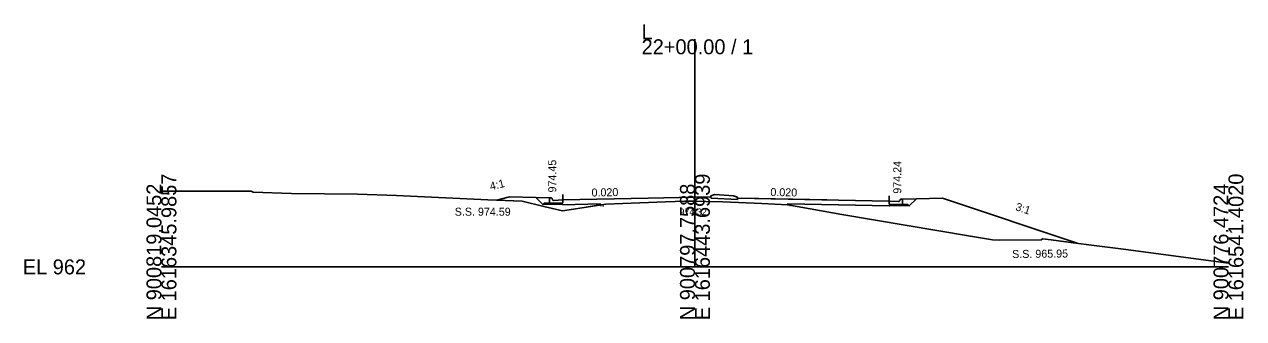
# Model space of a CAD drawing. Extents: x 1009 to 7438, y -1586 to 7964.
# Drawn here: x 2009.2 to 2237.7, y -86 to -30.8 of the extents above; entities that cross this region are included whole.
import ezdxf

# ---------------------------------------------------------------- set-up
doc = ezdxf.new("R2010")
doc.units = 0
for name, color, linetype in [('Exist Cross Section Cell', 7, 'Continuous'), ('Exist XS Center Line Elevation Label', 7, 'Continuous'), ('Exist XS Ground Line', 7, 'Continuous'), ('Prop XS Dump Level', 7, 'Continuous'), ('Prop XS Earthwork Shape', 7, 'Continuous'), ('Prop XS EOT Tick Mark', 7, 'Continuous'), ('Prop XS Finish Grade', 7, 'Continuous'), ('Prop XS Finish Grade CurbGutter', 7, 'Continuous'), ('Prop XS Finish Grade Earthwork', 7, 'Continuous'), ('Prop XS Finish Grade Pavement', 7, 'Continuous'), ('Prop XS Hydro Elevations', 7, 'Continuous'), ('Prop XS Pvmt Edge Slope', 7, 'Continuous'), ('Prop XS SE Text', 7, 'Continuous'), ('Prop XS Side Slope Text', 7, 'Continuous'), ('Prop XS SS Elevation Text', 7, 'Continuous'), ('Prop XS Subgrade CurbGutter', 7, 'Continuous'), ('Prop XS Subgrade Earthwork', 7, 'Continuous')]:
    doc.layers.add(name, color=color, linetype=linetype)

msp = doc.modelspace()

# ---------------------------------------------------------------- linework, layer by layer
at = {"layer": 'Exist Cross Section Cell'}
for p, q in [((2134.89, -76.27), (2134.89, -33.62)), ((2034.89, -76.27), (2134.89, -76.27)), ((2134.89, -76.27), (2234.89, -76.27))]:
    msp.add_line(p, q, dxfattribs=at)
at = {"layer": 'Exist XS Ground Line'}
for p, q in [((2034.89, -62.06), (2040.24, -62.05)), ((2040.24, -62.05), (2043.65, -62.06)), ((2043.65, -62.06), (2044.06, -62.08)), ((2044.06, -62.08), (2051.71, -62.09)), ((2051.71, -62.09), (2052.09, -62.24)), ((2052.09, -62.24), (2059.28, -62.49)), ((2059.28, -62.49), (2071.66, -62.67)), ((2071.66, -62.67), (2078.97, -62.92)), ((2078.97, -62.92), (2096.06, -63.69)), ((2096.06, -63.69), (2102.5, -63.94)), ((2102.5, -63.94), (2106.55, -64.95)), ((2129.35, -64.08), (2133.01, -63.98)), ((2133.01, -63.98), (2134.51, -63.94)), ((2134.51, -63.94), (2134.89, -63.95)), ((2134.89, -63.95), (2136.94, -64.01)), ((2106.55, -64.95), (2110.04, -65.76)), ((2110.04, -65.76), (2113.73, -65.21)), ((2113.73, -65.21), (2118.17, -64.51)), ((2118.17, -64.51), (2124.58, -64.26)), ((2124.58, -64.26), (2129.35, -64.08)), ((2136.94, -64.01), (2140.1, -64.07)), ((2140.1, -64.07), (2147.41, -64.42)), ((2147.41, -64.42), (2152.33, -64.66)), ((2152.33, -64.66), (2162.41, -66.43)), ((2162.41, -66.43), (2186.53, -70.54)), ((2186.53, -70.54), (2190.64, -71.2)), ((2190.64, -71.2), (2191.98, -71.27)), ((2191.98, -71.27), (2199.78, -71.23)), ((2199.78, -71.23), (2200.04, -71)), ((2200.04, -71), (2201.68, -71.21)), ((2201.68, -71.21), (2208.22, -72.06)), ((2208.22, -72.06), (2214.69, -72.9)), ((2214.69, -72.9), (2234.89, -75.57))]:
    msp.add_line(p, q, dxfattribs=at)
at = {"layer": 'Prop XS Dump Level'}
for p, q in [((2110.14, -63.7), (2126.14, -63.38)), ((2110.14, -63.7), (2126.14, -63.38)), ((2126.14, -63.38), (2134.89, -63.2)), ((2126.14, -63.38), (2134.89, -63.2)), ((2143.64, -63.38), (2159.64, -63.7)), ((2143.64, -63.38), (2159.64, -63.7))]:
    msp.add_line(p, q, dxfattribs=at)
at = {"layer": 'Prop XS Earthwork Shape'}
for points in [[(2110.04, -65.76), (2113.73, -65.21), (2117.14, -64.67), (2117.14, -64.47), (2110.14, -64.61), (2110.14, -64.53), (2106.39, -64.6), (2105.05, -63.26), (2100.14, -63.16), (2097.74, -63.76), (2102.5, -63.94), (2106.55, -64.95)], [(2181.31, -63.39), (2206.74, -71.87), (2201.68, -71.21), (2200.04, -71), (2199.78, -71.23), (2191.98, -71.27), (2190.64, -71.2), (2186.53, -70.54), (2162.41, -66.43), (2152.33, -64.66), (2152.28, -64.65), (2152.28, -64.46), (2171.31, -64.85), (2171.31, -64.76), (2175.06, -64.83), (2176.4, -63.49)]]:
    msp.add_lwpolyline(points, close=True, dxfattribs=at)
at = {"layer": 'Prop XS EOT Tick Mark'}
for p, q in [((2110.14, -63.7), (2110.14, -62.7)), ((2171.31, -63.93), (2171.31, -62.93))]:
    msp.add_line(p, q, dxfattribs=at)
at = {"layer": 'Prop XS Finish Grade'}
for p, q in [((2107.64, -63.32), (2105.05, -63.26)), ((2173.81, -63.55), (2176.4, -63.49))]:
    msp.add_line(p, q, dxfattribs=at)
at = {"layer": 'Prop XS Finish Grade CurbGutter'}
for p, q in [((2107.64, -63.32), (2107.89, -63.32)), ((2107.89, -63.32), (2108.02, -63.34)), ((2108.11, -63.44), (2108.02, -63.34)), ((2108.18, -63.69), (2108.11, -63.44)), ((2108.27, -63.78), (2108.18, -63.69)), ((2108.39, -63.8), (2108.27, -63.78)), ((2110.14, -63.7), (2108.39, -63.8)), ((2137.89, -62.97), (2138.64, -62.72)), ((2137.89, -63.14), (2137.89, -62.97)), ((2138.64, -62.72), (2142.14, -62.94)), ((2142.89, -63.19), (2142.14, -62.94)), ((2142.89, -63.36), (2142.89, -63.19)), ((2171.31, -63.93), (2173.06, -64.03)), ((2173.19, -64.01), (2173.28, -63.92)), ((2173.28, -63.92), (2173.34, -63.67)), ((2173.34, -63.67), (2173.44, -63.58)), ((2173.56, -63.55), (2173.44, -63.58)), ((2173.81, -63.55), (2173.56, -63.55)), ((2173.06, -64.03), (2173.19, -64.01))]:
    msp.add_line(p, q, dxfattribs=at)
at = {"layer": 'Prop XS Finish Grade Earthwork'}
for p, q in [((2100.14, -63.16), (2097.74, -63.76)), ((2105.05, -63.26), (2100.14, -63.16)), ((2176.4, -63.49), (2181.31, -63.39)), ((2181.31, -63.39), (2206.74, -71.87))]:
    msp.add_line(p, q, dxfattribs=at)
at = {"layer": 'Prop XS Finish Grade Pavement'}
for p, q in [((2110.14, -63.7), (2126.14, -63.38)), ((2126.14, -63.38), (2137.89, -63.14)), ((2142.89, -63.36), (2171.31, -63.93))]:
    msp.add_line(p, q, dxfattribs=at)
at = {"layer": 'Prop XS Pvmt Edge Slope'}
for p, q in [((2106.64, -64.35), (2106.39, -64.6)), ((2107.64, -64.33), (2106.64, -64.35)), ((2173.81, -64.56), (2174.81, -64.58)), ((2174.81, -64.58), (2175.06, -64.83))]:
    msp.add_line(p, q, dxfattribs=at)
at = {"layer": 'Prop XS Subgrade CurbGutter'}
for p, q in [((2107.64, -64.33), (2107.64, -63.32)), ((2110.14, -63.7), (2110.14, -64.28)), ((2137.89, -63.14), (2137.89, -63.39)), ((2137.9, -63.39), (2142.89, -63.61)), ((2142.89, -63.36), (2142.89, -63.61)), ((2171.31, -63.93), (2171.31, -64.51)), ((2173.81, -64.56), (2173.81, -63.55)), ((2110.14, -64.28), (2107.64, -64.33)), ((2171.31, -64.51), (2173.81, -64.56))]:
    msp.add_line(p, q, dxfattribs=at)
at = {"layer": 'Prop XS Subgrade Earthwork'}
for p, q in [((2106.39, -64.6), (2105.05, -63.26)), ((2175.06, -64.83), (2176.4, -63.49)), ((2110.14, -64.53), (2106.39, -64.6)), ((2117.14, -64.47), (2110.14, -64.61)), ((2110.14, -64.61), (2110.14, -64.53)), ((2117.14, -64.47), (2117.14, -64.67)), ((2152.28, -64.46), (2152.28, -64.65)), ((2152.28, -64.46), (2171.31, -64.85)), ((2171.31, -64.85), (2171.31, -64.76)), ((2171.31, -64.76), (2175.06, -64.83))]:
    msp.add_line(p, q, dxfattribs=at)

# ---------------------------------------------------------------- texts
at = {"layer": 'Exist Cross Section Cell'}
for s, p in [('L', (2124.89, -33.62)), ('22+00.00 / 1', (2124.89, -36.42)), ('EL 962', (2008.89, -77.67))]:
    msp.add_text(s, height=2.8, dxfattribs=at).set_placement(p)
for s, p in [('E 1616345.9857', (2037.69, -86.27)), ('E 1616443.6939', (2137.69, -86.27)), ('E 1616541.4020', (2237.69, -86.27)), ('N 900819.0452', (2034.89, -86.27)), ('N 900797.7588', (2134.89, -86.27)), ('N 900776.4724', (2234.89, -86.27))]:
    msp.add_text(s, height=2.8, rotation=90, dxfattribs=at).set_placement(p)
at = {"layer": 'Exist XS Center Line Elevation Label'}
msp.add_text('974.32', height=1.25, dxfattribs=at).set_placement((2131.99, -66.58))
at = {"layer": 'Prop XS Dump Level'}
for p in [(2117.14, -64.97), (2117.14, -64.97), (2152.28, -64.95), (2152.28, -64.95)]:
    msp.add_text('Eop', height=0.3, dxfattribs=at).set_placement(p)
at = {"layer": 'Prop XS Hydro Elevations'}
for s, p in [('974.45', (2108.89, -62.32)), ('974.24', (2173.56, -62.55))]:
    msp.add_text(s, height=1.5, rotation=90, dxfattribs=at).set_placement(p)
at = {"layer": 'Prop XS SE Text'}
for rotation, p in [(1.1458, (2115.52, -63.09)), (358.8542, (2149.02, -62.98))]:
    msp.add_text('0.020', height=1.5, rotation=rotation, dxfattribs=at).set_placement(p)
at = {"layer": 'Prop XS Side Slope Text'}
for s, rotation, p in [('4:1', 14.0362, (2096.64, -61.94)), ('3:1', 341.5651, (2194.85, -65.61))]:
    msp.add_text(s, height=1.5, rotation=rotation, dxfattribs=at).set_placement(p)
at = {"layer": 'Prop XS SS Elevation Text'}
msp.add_text('S.S. 974.59', height=1.5, dxfattribs=at).set_placement((2089.87, -66.68))
msp.add_text('S.S. 965.95', height=1.5, rotation=0.5729, dxfattribs=at).set_placement((2194.35, -74.61))

doc.saveas('drawing.dxf')
